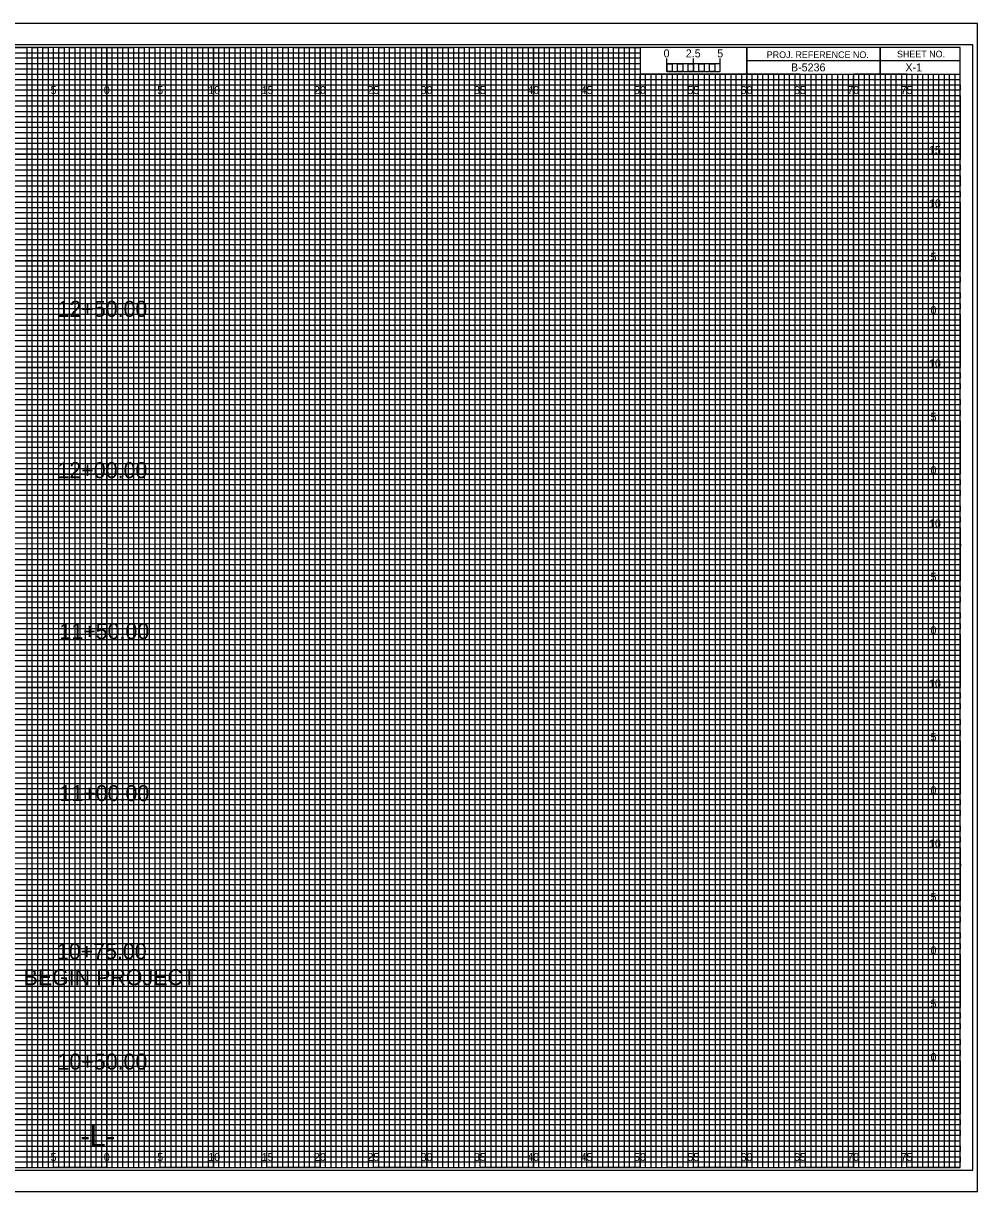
# Model space of a CAD drawing. Extents: x -7 to 162, y -2 to 107.
# Drawn here: x 72.2 to 161.7, y -2.3 to 107.3 of the extents above; entities that cross this region are included whole.
import ezdxf

# ---------------------------------------------------------------- set-up
doc = ezdxf.new("R2010")
doc.units = 0
for name, color, linetype in [('Prop XS Alignment Label', 7, 'Continuous'), ('Prop XS Bar Scale Labels', 7, 'Continuous'), ('Prop XS Elevation Labels', 7, 'Continuous'), ('Prop XS Offset Labels', 7, 'Continuous'), ('Prop XS Project Number', 7, 'Continuous'), ('Prop XS Sheet Number', 7, 'Continuous'), ('Prop XS Station Labels', 7, 'Continuous'), ('Sheet Cross Section CELL', 7, 'Continuous'), ('Sheet Cross Section Grid Major CELL', 7, 'Continuous'), ('Sheet Cross Section Grid Middle CELL', 7, 'Continuous'), ('Sheet Cross Section Grid Minor 1 CELL', 7, 'Continuous'), ('Sheet Cross Section Grid Minor 2 CELL', 7, 'Continuous'), ('Sheet Cross Section Scale CELL', 7, 'Continuous'), ('Sheet Cutting Line CELL', 7, 'Continuous'), ('Sheet DOT Grid CELL', 7, 'Continuous'), ('Sheet Plot Border Inside CELL', 7, 'Continuous'), ('Sheet Plot Border Outside CELL', 7, 'Continuous')]:
    doc.layers.add(name, color=color, linetype=linetype)

msp = doc.modelspace()

# ---------------------------------------------------------------- linework, layer by layer
at = {"layer": 'Sheet Cross Section CELL'}
for p, q in [((152.5, 105), (152.5, 102.5)), ((152.5, 102.5), (152.5, 105)), ((160, 103.75), (140, 103.75)), ((140, 103.75), (140, 102.5)), ((140, 102.5), (160, 102.5))]:
    msp.add_line(p, q, dxfattribs=at)
for points in [[(160, 105), (0, 105), (0, 0), (160, 0)], [(140, 105), (130, 105), (130, 102.52), (140, 102.52)], [(160, 105), (140, 105), (140, 102.5), (160, 102.5)]]:
    msp.add_lwpolyline(points, close=True, dxfattribs=at)
at = {"layer": 'Sheet Cross Section Grid Major CELL'}
for p, q in [((75, 105), (70, 105)), ((75, 0), (75, 105)), ((85, 105), (80, 105)), ((80, 105), (80, 0)), ((85, 0), (85, 105)), ((95, 105), (90, 105)), ((90, 105), (90, 0)), ((95, 0), (95, 105)), ((105, 105), (100, 105)), ((100, 105), (100, 0)), ((105, 0), (105, 105)), ((115, 105), (110, 105)), ((110, 105), (110, 0)), ((115, 0), (115, 105)), ((125, 105), (120, 105)), ((120, 105), (120, 0)), ((125, 0), (125, 105)), ((130, 105), (130, 0)), ((135, 0), (135, 102.5)), ((145, 102.5), (140, 102.5)), ((140, 102.5), (140, 0)), ((145, 0), (145, 102.5)), ((155, 102.5), (150, 102.5)), ((150, 102.5), (150, 0)), ((155, 0), (155, 102.5)), ((80, 0), (75, 0)), ((90, 0), (85, 0)), ((100, 0), (95, 0)), ((110, 0), (105, 0)), ((120, 0), (115, 0)), ((130, 0), (125, 0)), ((140, 0), (135, 0)), ((150, 0), (145, 0)), ((160, 0), (155, 0)), ((160, 0), (160, 0))]:
    msp.add_line(p, q, dxfattribs=at)
for points in [[(0, 100), (160, 100), (160, 95), (0, 95)], [(0, 90), (160, 90), (160, 85), (0, 85)], [(0, 80), (160, 80), (160, 75), (0, 75)], [(0, 70), (160, 70), (160, 65), (0, 65)], [(0, 60), (160, 60), (160, 55), (0, 55)], [(0, 50), (160, 50), (160, 45), (0, 45)], [(0, 40), (160, 40), (160, 35), (0, 35)], [(0, 30), (160, 30), (160, 25), (0, 25)], [(0, 20), (160, 20), (160, 15), (0, 15)], [(0, 10), (160, 10), (160, 5), (0, 5)]]:
    msp.add_lwpolyline(points, dxfattribs=at)
at = {"layer": 'Sheet Cross Section Grid Middle CELL'}
for points in [[(67.5, 105), (72.5, 105), (72.5, 0), (77.5, 0), (77.5, 105), (82.5, 105), (82.5, 0), (87.5, 0), (87.5, 105), (92.5, 105), (92.5, 0), (97.5, 0), (97.5, 105), (102.5, 105), (102.5, 0), (107.5, 0), (107.5, 105), (112.5, 105), (112.5, 0), (117.5, 0), (117.5, 105), (122.5, 105), (122.5, 0), (127.5, 0), (127.5, 105), (129.97, 105), (130, 105), (130, 102.5), (132.5, 102.5), (132.5, 0), (137.5, 0), (137.5, 102.5), (142.5, 102.5), (142.5, 0), (147.5, 0), (147.5, 102.5), (152.5, 102.5), (152.5, 0), (157.5, 0), (157.5, 102.5)], [(0, 102.5), (137.5, 102.5)], [(0, 92.5), (160, 92.5), (160, 97.5), (0, 97.5)], [(0, 82.5), (160, 82.5), (160, 87.5), (0, 87.5)], [(0, 72.5), (160, 72.5), (160, 77.5), (0, 77.5)], [(0, 62.5), (160, 62.5), (160, 67.5), (0, 67.5)], [(0, 52.5), (160, 52.5), (160, 57.5), (0, 57.5)], [(0, 42.5), (160, 42.5), (160, 47.5), (0, 47.5)], [(0, 32.5), (160, 32.5), (160, 37.5), (0, 37.5)], [(0, 22.5), (160, 22.5), (160, 27.5), (0, 27.5)], [(0, 12.5), (160, 12.5), (160, 17.5), (0, 17.5)], [(0, 2.5), (160, 2.5), (160, 7.5), (0, 7.5)]]:
    msp.add_lwpolyline(points, dxfattribs=at)
at = {"layer": 'Sheet Cross Section Grid Minor 1 CELL'}
for p, q in [((0, 104.5), (130, 104.5)), ((130, 104.5), (130, 103.99)), ((130, 103.99), (0, 103.99)), ((0, 103.5), (130, 103.5)), ((130, 102.95), (0, 102.95)), ((130, 103.5), (130, 102.95)), ((0, 102), (160, 102))]:
    msp.add_line(p, q, dxfattribs=at)
for points in [[(0, 101.5), (135, 101.5), (160, 101.5), (160, 101), (0, 101)], [(0, 100.5), (160, 100.5), (160, 99.5), (0, 99.5)], [(0, 99), (160, 99), (160, 98.5), (0, 98.49)], [(0, 98), (160, 98), (160, 97), (0, 97)], [(0, 96.5), (160, 96.5), (160, 96), (0, 96)], [(0, 95.5), (160, 95.5), (160, 94.5), (0, 94.5)], [(0, 94), (160, 94), (160, 93.5), (0, 93.5)], [(0, 93), (160, 93), (160, 92), (0, 92)], [(0, 91.5), (160, 91.5), (160, 91), (0, 91)], [(0, 90.5), (160, 90.5), (160, 89.5), (0, 89.5)], [(0, 89), (160, 89), (160, 88.5), (0, 88.5)], [(0, 88), (160, 88), (160, 86.98), (160, 86.5), (160, 86), (0, 86)], [(0, 87), (160, 87), (160, 86.5), (0, 86.5)], [(0, 85.5), (160, 85.5), (160, 84.5), (0, 84.52)], [(0, 84.52), (160, 84.5), (160, 84), (0, 84)], [(0, 83.5), (160, 83.5), (160, 83), (0, 83)], [(0, 82), (160, 82), (160, 81.5), (0, 81.5)], [(0, 81), (160, 81), (160, 80.5), (0, 80.5)], [(-0.04, 79.45), (160, 79.45), (160, 78.94), (-0.04, 78.94)], [(0, 78.5), (160, 78.5), (160, 78), (0, 78)], [(0, 77), (160, 77), (160, 76.5), (0, 76.5)], [(0, 76), (160, 76), (160, 75.5), (0, 75.5)], [(0, 74.5), (160, 74.5), (160, 74), (0, 74)], [(0, 73.5), (160, 73.5), (160, 73), (0, 73)], [(0, 72), (160, 72), (160, 71.5), (0, 71.5)], [(0, 71), (160, 71), (160, 70.5), (0, 70.5)], [(0, 69.5), (160, 69.5), (160, 68.99), (0, 69)], [(0, 68.5), (160, 68.5), (160, 68), (0, 68)], [(0, 67), (160, 67), (160, 66.5), (0, 66.5)], [(0, 66), (160, 66), (160, 65.5), (0, 65.5)], [(0, 64.5), (160, 64.5), (160, 64), (0, 64)], [(0, 63.5), (160, 63.5), (160, 63), (0, 63)], [(0, 62), (160, 62), (160, 61.5), (0, 61.5)], [(0, 61), (160, 61), (160, 60.5), (0, 60.5)], [(0, 59.5), (160, 59.5), (160, 59), (0, 59)], [(0, 58.5), (160.03, 58.45), (160, 58), (0, 58)], [(0, 57), (160, 57), (160, 56.5), (0, 56.5)], [(0, 56), (160, 56), (160, 55.5), (0, 55.5)], [(0, 54.5), (160, 54.5), (160, 54), (0, 54)], [(0, 53.5), (160, 53.5), (160, 53), (0, 53)], [(0, 52), (160, 52), (160, 51.5), (0, 51.5)], [(0, 51), (160, 51), (160, 50.5), (0, 50.5)], [(0, 49.5), (160, 49.5), (160, 49), (0, 49)], [(0, 48.5), (160, 48.5), (160, 48), (0, 48)], [(0, 47), (160, 47), (160, 46.5), (0, 46.5)], [(0, 46), (160, 46), (160, 45.5), (0, 45.5)], [(0, 44.5), (160, 44.5), (160, 44), (0, 44)], [(0, 43.5), (160, 43.5), (160, 43), (0, 43)], [(0, 42), (160, 42), (160, 41.5), (0, 41.5)], [(0, 41), (160, 41), (160, 40.5), (0, 40.5)], [(0, 39.5), (160, 39.5), (160, 38.99), (0, 39)], [(0, 38.5), (160, 38.5), (160, 38), (0, 38)], [(0, 37), (160, 37), (160, 36.5), (0, 36.5)], [(0, 36), (160, 36), (160, 35.5), (0, 35.5)], [(0, 34.5), (160, 34.5), (160, 34), (0, 34)], [(0, 33.5), (160, 33.5), (160, 33), (0, 33)], [(0, 32), (160, 32), (160, 31.5), (0, 31.5)], [(0, 31), (160, 31), (160, 30.5), (0, 30.5)], [(0, 29.5), (160, 29.5), (160, 29), (0, 29)], [(0, 28.5), (160.03, 28.46), (160, 28), (0, 28)], [(0, 27), (160, 27), (160, 26.5), (0, 26.5)], [(0, 26), (160, 26), (160, 25.5), (0, 25.5)], [(0, 24.5), (160, 24.5), (160, 24), (0, 24)], [(0, 23.5), (160, 23.5), (160, 23), (0, 23)], [(0, 22), (160, 22), (160, 21.5), (0, 21.5)], [(0, 21), (160, 21), (160, 20.5), (0, 20.5)], [(0, 19.5), (160, 19.5), (160, 19), (0, 19)], [(0, 18.5), (160, 18.5), (160, 18), (0, 18)], [(0, 17), (160, 17), (160, 16.5), (0, 16.5)], [(0, 16), (160, 16), (160, 15.5), (0, 15.5)], [(0, 14.5), (160, 14.5), (160, 14), (0, 14)], [(0, 13.5), (160, 13.5), (160, 13), (0, 13)], [(0, 12), (160, 12), (160, 11.5), (0, 11.5)], [(0, 11), (160, 11), (160, 10.5), (0, 10.5)], [(0, 9.5), (160, 9.5), (160, 9), (0, 9)], [(0, 8.5), (160, 8.5), (160, 8), (0, 8)], [(0, 7), (160, 7), (160, 6.5), (0, 6.5)], [(0, 6), (160, 6), (160, 5.5), (0, 5.5)], [(0, 4.5), (160, 4.5), (160, 4), (0, 4)], [(0, 3.5), (160, 3.5), (160, 3), (0, 3)], [(0, 2), (160, 2), (160, 1.5), (0, 1.5)], [(0, 1), (160, 1), (160, 0.5), (0, 0.5)]]:
    msp.add_lwpolyline(points, dxfattribs=at)
at = {"layer": 'Sheet Cross Section Grid Minor 2 CELL'}
for p, q in [((133.5, 102.5), (133, 102.5)), ((133, 102.5), (133, 0)), ((133.5, 0), (133.5, 102.5)), ((134.5, 102.5), (134, 102.5)), ((134, 102.5), (134, 0)), ((134.5, 0), (134.5, 102.5)), ((133, 0), (132.5, 0)), ((134, 0), (133.5, 0))]:
    msp.add_line(p, q, dxfattribs=at)
for points in [[(72.5, 0), (73, 0), (73, 105), (73.5, 105), (73.5, 0)], [(73.5, 0), (74, 0), (74, 105), (74.5, 105), (74.5, 0)], [(75, 0), (75.5, 0), (75.5, 105), (76, 105), (76, 0)], [(76, 0), (76.5, 0), (76.5, 105), (77, 105), (77, 0)], [(77.5, 0), (78, 0), (78, 105), (78.5, 105), (78.5, 0)], [(78.5, 0), (79, 0), (79, 105), (79.5, 105), (79.5, 0)], [(80, 0), (80.5, 0), (80.5, 105), (81, 105), (81, 0)], [(81, 0), (81.5, 0), (81.5, 105), (82, 105), (82, 0)], [(82.5, 0), (83, 0), (83, 105), (83.5, 105), (83.5, 0)], [(83.5, 0), (84, 0), (84, 105), (84.5, 105), (84.5, 0)], [(85, 0), (85.5, 0), (85.5, 105), (86, 105), (86, 0)], [(86, 0), (86.5, 0), (86.5, 105), (87, 105), (87, 0)], [(87.5, 0), (88, 0), (88, 105), (88.5, 105), (88.5, 0)], [(88.5, 0), (89, 0), (89, 105), (89.5, 105), (89.5, 0)], [(90, 0), (90.5, 0), (90.5, 105), (91, 105), (91, 0)], [(91, 0), (91.5, 0), (91.5, 105), (92, 105), (92, 0)], [(92.5, 0), (93, 0), (93, 105), (93.5, 105), (93.5, 0)], [(93.5, 0), (94, 0), (94, 105), (94.5, 105), (94.5, 0)], [(95, 0), (95.5, 0), (95.5, 105), (96, 105), (96, 0)], [(96, 0), (96.5, 0), (96.5, 105), (97, 105), (97, 0)], [(97.5, 0), (98, 0), (98, 105), (98.5, 105), (98.5, 0)], [(98.5, 0), (99, 0), (99, 105), (99.5, 105), (99.5, 0)], [(100, 0), (100.5, 0), (100.5, 105), (101, 105), (101, 0)], [(101, 0), (101.5, 0), (101.5, 105), (102, 105), (102, 0)], [(102.5, 0), (103, 0), (103, 105), (103.5, 105), (103.5, 0)], [(103.5, 0), (104, 0), (104, 105), (104.5, 105), (104.5, 0)], [(105, 0), (105.5, 0), (105.5, 105), (106, 105), (106, 0)], [(106, 0), (106.5, 0), (106.5, 105), (107, 105), (107, 0)], [(107.5, 0), (108, 0), (108, 105), (108.5, 105), (108.5, 0)], [(108.5, 0), (109, 0), (109, 105), (109.5, 105), (109.5, 0)], [(110, 0), (110.5, 0), (110.5, 105), (111, 105), (111, 0)], [(111, 0), (111.5, 0), (111.5, 105), (112, 105), (112, 0)], [(112.5, 0), (113, 0), (113, 105), (113.5, 105), (113.5, 0)], [(113.5, 0), (114, 0), (114, 105), (114.5, 105), (114.5, 0)], [(115, 0), (115.5, 0), (115.5, 105), (116, 105), (116, 0)], [(116, 0), (116.5, 0), (116.5, 105), (117, 105), (117, 0)], [(117.5, 0), (118, 0), (118, 105), (118.5, 105), (118.5, 0)], [(118.5, 0), (119, 0), (119, 105), (119.5, 105), (119.5, 0)], [(120, 0), (120.5, 0), (120.5, 105), (121, 105), (121, 0)], [(121, 0), (121.5, 0), (121.5, 105), (122, 105), (122, 0)], [(122.5, 0), (123, 0), (123, 105), (123.5, 105), (123.5, 0)], [(123.5, 0), (124, 0), (124, 105), (124.5, 105), (124.5, 0)], [(125, 0), (125.5, 0), (125.5, 105), (126, 105), (126, 0)], [(126, 0), (126.5, 0), (126.5, 105), (127, 105), (127, 0)], [(127.5, 0), (128, 0), (128, 105), (128.5, 105), (128.5, 0)], [(128.5, 0), (129, 0), (129, 105), (129.5, 105), (129.5, 0)], [(130, 0), (130.5, 0), (130.5, 102.5), (131.01, 102.5), (131.01, 0)], [(131, 0), (131.5, 0), (131.5, 102.5), (132, 102.5), (132, 0)], [(135, 0), (135.49, 0), (135.49, 102.5), (136, 102.5), (136, 0)], [(136, 0), (136.5, 0), (136.5, 102.5), (137.03, 102.5), (137.03, 0)], [(137.5, 0), (138, 0), (138, 102.5), (138.5, 102.5), (138.5, 0)], [(138.5, 0), (139, 0), (139, 102.5), (139.5, 102.5), (139.5, 0)], [(140, 0), (140.5, 0), (140.5, 102.5), (141, 102.5), (141, 0)], [(141, 0), (141.5, 0), (141.5, 102.5), (142, 102.5), (142, 0)], [(142.5, 0), (143, 0), (143, 102.5), (143.5, 102.5), (143.5, 0)], [(143.5, 0), (144, 0), (144, 102.5), (144.5, 102.5), (144.5, 0)], [(145, 0), (145.5, 0), (145.5, 102.5), (146, 102.5), (146, 0)], [(146, 0), (146.5, 0), (146.5, 102.5), (147, 102.5), (147, 0)], [(147.5, 0), (148, 0), (148, 102.5), (148.5, 102.5), (148.5, 0)], [(148.5, 0), (149, 0), (149, 102.5), (149.5, 102.5), (149.5, 0)], [(150, 0), (150.5, 0), (150.5, 102.5), (151, 102.5), (151, 0)], [(151, 0), (151.5, 0), (151.5, 102.5), (152, 102.5), (152, 0)], [(152.5, 0), (153, 0), (153, 102.5), (153.5, 102.5), (153.5, 0)], [(153.5, 0), (154, 0), (154, 102.5), (154.5, 102.5), (154.5, 0)], [(155, 0), (155.5, 0), (155.5, 102.5), (156, 102.5), (156, 0)], [(156, 0), (156.5, 0), (156.5, 102.5), (157, 102.5), (157, 0)], [(157.5, 0), (158, 0), (158, 102.5), (158.5, 102.5), (158.5, 0)], [(158.5, 0), (159, 0), (159, 102.5), (159.5, 102.5), (159.5, 0)]]:
    msp.add_lwpolyline(points, dxfattribs=at)
at = {"layer": 'Sheet Cross Section Scale CELL'}
for p, q in [((132.5, 102.75), (132.5, 103.95)), ((132.5, 103.45), (132.5, 103.95)), ((135, 102.75), (135, 103.95)), ((137.5, 102.75), (137.5, 103.95)), ((137.5, 103.45), (137.5, 103.95))]:
    msp.add_line(p, q, dxfattribs=at)
for points in [[(137.5, 103.45), (132.5, 103.45), (132.5, 102.75), (137.5, 102.75)], [(132.5, 103.45), (133, 103.45), (133, 102.75), (132.5, 102.75)], [(133.5, 103.45), (134, 103.45), (134, 102.75), (133.5, 102.75)], [(134.5, 103.45), (135, 103.45), (135, 102.75), (134.5, 102.75)], [(135.5, 103.45), (136, 103.45), (136, 102.75), (135.5, 102.75)], [(136.5, 103.45), (137, 103.45), (137, 102.75), (136.5, 102.75)]]:
    msp.add_lwpolyline(points, close=True, dxfattribs=at)
at = {"layer": 'Sheet Cutting Line CELL'}
for p, q in [((161.65, 107.25), (-6.7, 107.25)), ((-6.7, -2.25), (161.65, -2.25))]:
    msp.add_line(p, q, dxfattribs=at)
at = {"layer": 'Sheet DOT Grid CELL'}
for p, q in [((75, 0), (75, 105)), ((80, 0), (80, 105)), ((85, 0), (85, 105)), ((90, 0), (90, 105)), ((95, 0), (95, 105)), ((100, 0), (100, 105)), ((105, 0), (105, 105)), ((110, 0), (110, 105)), ((115, 0), (115, 105)), ((120, 0), (120, 105)), ((125, 0), (125, 105)), ((130, 0), (130, 102.34)), ((135, 0), (135, 102.34)), ((140, 0), (140, 102.34)), ((145, 0), (145, 102.34)), ((150, 0), (150, 102.34)), ((155, 0), (155, 102.34)), ((0, 100), (160, 100)), ((0, 95), (160, 95)), ((0, 90), (160, 90)), ((0, 85), (160, 85)), ((0, 80), (160, 80)), ((0, 75), (160, 75)), ((0, 70), (160, 70)), ((0, 65), (160, 65)), ((0, 60), (160, 60)), ((0, 55), (160, 55)), ((0, 50), (160, 50)), ((0, 45), (160, 45)), ((0, 40), (160, 40)), ((0, 35), (160, 35)), ((0, 30), (160, 30)), ((0, 25), (160, 25)), ((0, 20), (160, 20)), ((0, 15), (160, 15)), ((0, 10), (160, 10)), ((0, 5), (160, 5))]:
    msp.add_line(p, q, dxfattribs=at)
at = {"layer": 'Sheet Plot Border Inside CELL'}
msp.add_lwpolyline([(-5.4, -0.25), (161.2, -0.25), (161.2, 105.25), (-5.4, 105.25)], close=True, dxfattribs=at)
at = {"layer": 'Sheet Plot Border Outside CELL'}
msp.add_lwpolyline([(-6.7, -2.25), (161.65, -2.25), (161.65, 107.25), (-6.7, 107.25)], close=True, dxfattribs=at)

# ---------------------------------------------------------------- texts
at = {"layer": 'Prop XS Alignment Label'}
msp.add_text('-L-', height=2, dxfattribs=at).set_placement((77.53, 2))
at = {"layer": 'Prop XS Bar Scale Labels'}
for s, p in [('2.5', (134.29, 104.06)), ('5', (137.24, 104.06))]:
    msp.add_text(s, height=0.75, dxfattribs=at).set_placement(p)
at = {"layer": 'Prop XS Elevation Labels'}
for s, p in [('15', (157.08, 95)), ('10', (157.09, 90)), ('5', (157.23, 85)), ('0', (157.23, 80)), ('10', (157.09, 75)), ('5', (157.23, 70)), ('0', (157.23, 65)), ('10', (157.09, 60)), ('5', (157.23, 55)), ('0', (157.23, 50)), ('10', (157.09, 45)), ('5', (157.23, 40)), ('0', (157.23, 35)), ('10', (157.09, 30)), ('5', (157.23, 25)), ('0', (157.23, 20)), ('5', (157.23, 15)), ('0', (157.23, 10))]:
    msp.add_text(s, height=0.75, dxfattribs=at).set_placement(p)
at = {"layer": 'Prop XS Offset Labels'}
for s, p in [('5', (74.74, 100.62)), ('0', (79.73, 100.62)), ('0', (79.73, 100.62)), ('5', (84.74, 100.62)), ('10', (89.52, 100.62)), ('15', (94.53, 100.62)), ('20', (99.43, 100.62)), ('25', (104.44, 100.62)), ('30', (109.43, 100.62)), ('35', (114.44, 100.62)), ('40', (119.43, 100.62)), ('45', (124.44, 100.62)), ('50', (129.43, 100.62)), ('55', (134.44, 100.62)), ('60', (139.43, 100.62)), ('65', (144.44, 100.62)), ('70', (149.43, 100.62)), ('75', (154.44, 100.62)), ('5', (74.74, 0.62)), ('0', (79.73, 0.62)), ('0', (79.73, 0.62)), ('5', (84.74, 0.62)), ('10', (89.52, 0.62)), ('15', (94.53, 0.62)), ('20', (99.43, 0.62)), ('25', (104.44, 0.62)), ('30', (109.43, 0.62)), ('35', (114.44, 0.62)), ('40', (119.43, 0.62)), ('45', (124.44, 0.62)), ('50', (129.43, 0.62)), ('55', (134.44, 0.62)), ('60', (139.43, 0.62)), ('65', (144.44, 0.62)), ('70', (149.43, 0.62)), ('75', (154.44, 0.62))]:
    msp.add_text(s, height=0.75, dxfattribs=at).set_placement(p)
at = {"layer": 'Prop XS Project Number'}
msp.add_text('B-5236', height=0.75, dxfattribs=at).set_placement((144.15, 102.75))
at = {"layer": 'Prop XS Sheet Number'}
msp.add_text('X-1', height=0.75, dxfattribs=at).set_placement((154.88, 102.75))
at = {"layer": 'Prop XS Station Labels'}
for s, p in [('12+50.00', (75.39, 79.74)), ('12+00.00', (75.39, 64.62)), ('11+50.00', (75.57, 49.53)), ('11+00.00', (75.57, 34.35)), ('10+75.00', (75.33, 19.53)), ('BEGIN PROJECT', (72.21, 17.1)), ('10+50.00', (75.39, 9.19))]:
    msp.add_text(s, height=1.5, dxfattribs=at).set_placement(p)
at = {"layer": 'Sheet Cross Section CELL'}
for s, p in [('PROJ. REFERENCE NO.', (141.88, 104)), ('SHEET NO.', (154.09, 104.06))]:
    msp.add_text(s, height=0.625, dxfattribs=at).set_placement(p)
at = {"layer": 'Sheet Cross Section Scale CELL'}
msp.add_text('0', height=0.75, dxfattribs=at).set_placement((132.21, 104.06))

doc.saveas('drawing.dxf')
